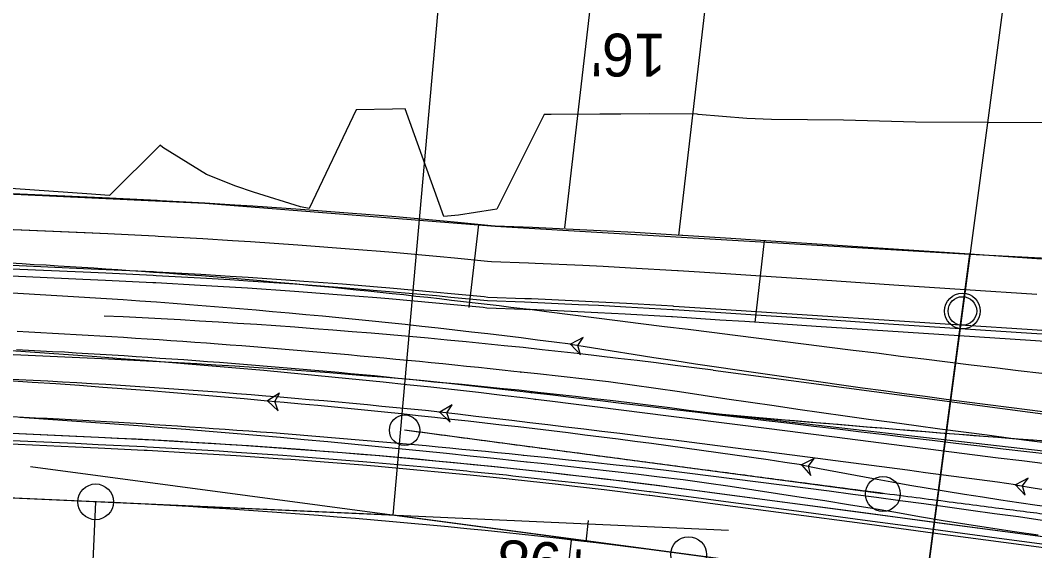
# Model space of a CAD drawing. Extents: x -70 to 701944, y -4 to 666871.
# Drawn here: x 667714.7 to 667856.7, y 656552.8 to 656627 of the extents above; entities that cross this region are included whole.
import ezdxf

# ---------------------------------------------------------------- set-up
doc = ezdxf.new("R2010")
doc.units = 0
for name, color, linetype in [('R_Detour', 7, 'Continuous'), ('R_Draft', 7, 'Continuous'), ('R_Drive', 7, 'Continuous'), ('R_Horz Alg', 7, 'Continuous'), ('R_Horz Alg Annot', 7, 'Continuous'), ('R_No Plot', 7, 'Continuous'), ('R_Proposed Const Limits', 7, 'Continuous'), ('R_Proposed Road', 7, 'Continuous'), ('R_ROW', 7, 'Continuous'), ('R_Striping', 7, 'Continuous'), ('R_Water', 7, 'Continuous'), ('T_Indications', 7, 'Continuous'), ('T_Vehicle Path Lt Minor', 7, 'Continuous'), ('T_Vehicle Path Rt', 7, 'Continuous')]:
    doc.layers.add(name, color=color, linetype=linetype)

msp = doc.modelspace()

# ---------------------------------------------------------------- linework, layer by layer
at = {"layer": 'R_Detour'}
msp.add_line((667852.89, 656633.86), (667841.43, 656547.81), dxfattribs=at)
at = {"layer": 'R_Draft'}
msp.add_line((667835.43, 656560.72), (667768.5, 656569.64), dxfattribs=at)
for centre, radius in [((667768.5, 656569.64), 2.13), ((667835.43, 656560.72), 2.44)]:
    msp.add_circle(centre, radius, dxfattribs=at)
msp.add_open_spline([(668503.19, 656560.73), (668456.49, 656569.75), (668425.89, 656581.27), (668346.17, 656570.41), (668185.6, 656628.5), (667984.84, 656548.03), (667888.17, 656554.09), (667835.43, 656560.72), (667768.5, 656569.64)], degree=2, dxfattribs=at)
at = {"layer": 'R_Drive'}
for p, q in [((667796.37, 656645.62), (667790.86, 656597.92)), ((667811.01, 656632.92), (667806.84, 656596.86)), ((667778.83, 656598.4), (667777.5, 656586.82)), ((667818.84, 656596.14), (667817.52, 656584.72))]:
    msp.add_line(p, q, dxfattribs=at)
at = {"layer": 'R_Horz Alg'}
for p, q in [((667725.26, 656559.62), (664961.47, 656684.5)), ((667766.92, 656557.74), (667725.26, 656559.62)), ((667808.24, 656552.24), (667766.92, 656557.74))]:
    msp.add_line(p, q, dxfattribs=at)
msp.add_lwpolyline([(667791.28, 656549.31), (667791.85, 656554.27)], dxfattribs=at)
for centre in [(667725.26, 656559.62), (667808.24, 656552.24)]:
    msp.add_circle(centre, 2.5, dxfattribs=at)
msp.add_arc((667682.16, 655605.67), 954.93, 82.41302, 87.41302, dxfattribs=at)
at = {"layer": 'R_Horz Alg Annot'}
for points in [[(667766.92, 656557.74), (667781.69, 656723.66)], [(667725.26, 656559.62), (667717.07, 656378.27)]]:
    msp.add_lwpolyline(points, dxfattribs=at)
at = {"layer": 'R_No Plot'}
for p, q in [((667813.84, 656555.62), (664810.54, 656691.32)), ((667725.26, 656559.62), (664961.47, 656684.5)), ((668021.72, 656523.8), (667716.14, 656564.5))]:
    msp.add_line(p, q, dxfattribs=at)
for points in [[(667694.03, 656603.58), (667740.56, 656601.38), (667781.16, 656598.17), (667847.62, 656594.24), (667841.43, 656547.81), (667766.92, 656557.74), (667692.11, 656561.12)], [(667847.62, 656594.24), (667899.28, 656591.58), (667960.86, 656591.75), (667973.35, 656591.19), (667970.89, 656536.74), (667900.78, 656539.91), (667841.43, 656547.81)], [(667692.11, 656561.12), (667689.65, 656506.68), (667773.86, 656501.24), (667833.59, 656488.96), (667841.45, 656547.81), (667766.92, 656557.74)]]:
    msp.add_lwpolyline(points, close=True, dxfattribs=at)
msp.add_circle((667846.56, 656586.31), 2.5, dxfattribs=at)
msp.add_arc((667682.16, 655605.67), 954.93, 82.41302, 87.41302, dxfattribs=at)
at = {"layer": 'R_Proposed Const Limits'}
for points in [[(667860.16, 656612.65), (667850.07, 656612.69), (667839.99, 656612.71), (667829.94, 656612.99), (667819.86, 656613.07), (667816.37, 656613.25), (667809.56, 656613.81), (667809.45, 656613.82), (667802.7, 656613.88), (667798.74, 656613.85), (667795.84, 656613.82), (667788.99, 656613.81), (667788.05, 656613.79), (667781.4, 656600.57), (667780.82, 656600.46), (667776.06, 656599.72), (667774, 656599.52), (667768.56, 656614.6), (667766.81, 656614.54), (667761.73, 656614.44), (667755.16, 656600.65), (667753.95, 656600.9), (667747.37, 656602.93), (667744.89, 656603.79), (667740.79, 656605.39), (667734.68, 656609.2), (667734.27, 656609.49), (667727.2, 656602.47)], [(667727.2, 656602.47), (667724.02, 656602.69), (667714.04, 656603.41), (667704.06, 656603.99), (667694.07, 656604.33), (667684.08, 656604.85), (667674.08, 656605.17)]]:
    msp.add_lwpolyline(points, dxfattribs=at)
at = {"layer": 'R_Proposed Road'}
for p, q in [((667725.67, 656568.61), (667418.1, 656582.51)), ((667860.64, 656554.34), (667809.43, 656561.16))]:
    msp.add_line(p, q, dxfattribs=at)
for points in [[(667857.62, 656593.58), (667847.62, 656594.24), (667837.62, 656594.9), (667827.61, 656595.56), (667817.61, 656596.22), (667814.13, 656596.45), (667807.42, 656596.89), (667807.31, 656596.89), (667800.72, 656597.28), (667796.85, 656597.49), (667794.01, 656597.63), (667787.3, 656597.93), (667786.39, 656597.97), (667781.16, 656598.17), (667780.6, 656598.23), (667775.96, 656598.68), (667773.94, 656598.86), (667767.27, 656599.46), (667765.55, 656599.6), (667760.59, 656600.01), (667755.14, 656600.42), (667753.92, 656600.51), (667747.24, 656600.97), (667744.72, 656601.13), (667740.56, 656601.38), (667734.29, 656601.73), (667733.87, 656601.75), (667727.18, 656602.08), (667724, 656602.22), (667714.01, 656602.67)], [(667856.96, 656588.62), (667846.96, 656589.28), (667836.95, 656589.94), (667826.95, 656590.6), (667816.95, 656591.26), (667813.47, 656591.49), (667806.8, 656591.93), (667806.69, 656591.93), (667800.12, 656592.32), (667796.27, 656592.52), (667793.45, 656592.66), (667786.78, 656592.96), (667785.86, 656593), (667780.66, 656593.2), (667780.11, 656593.25), (667775.49, 656593.7), (667773.48, 656593.89), (667766.84, 656594.48), (667765.14, 656594.62), (667760.2, 656595.02), (667754.78, 656595.44), (667753.56, 656595.52), (667746.91, 656595.98), (667744.41, 656596.14), (667740.26, 656596.39), (667734.03, 656596.74), (667733.61, 656596.76), (667726.96, 656597.08), (667723.78, 656597.23), (667713.79, 656597.68)], [(667864.41, 656582.63), (667856.23, 656583.17), (667846.23, 656583.83), (667836.23, 656584.49), (667826.23, 656585.15), (667816.23, 656585.81), (667812.75, 656586.04), (667806.11, 656586.47), (667806, 656586.48), (667799.47, 656586.85), (667795.64, 656587.06), (667792.83, 656587.19), (667786.2, 656587.49), (667785.29, 656587.53), (667780.11, 656587.72), (667779.57, 656587.78), (667774.97, 656588.22), (667772.97, 656588.41), (667766.37, 656589), (667764.68, 656589.14), (667759.77, 656589.54), (667754.37, 656589.95), (667753.16, 656590.04), (667746.55, 656590.49), (667744.06, 656590.65), (667739.94, 656590.9), (667733.74, 656591.25), (667733.33, 656591.27), (667726.71, 656591.59), (667723.53, 656591.73), (667713.54, 656592.18)], [(667864.47, 656583.13), (667856.3, 656583.67), (667846.3, 656584.33), (667836.29, 656584.98), (667826.29, 656585.64), (667816.29, 656586.3), (667812.81, 656586.53), (667806.17, 656586.96), (667806.06, 656586.97), (667799.53, 656587.35), (667795.7, 656587.55), (667792.89, 656587.69), (667786.25, 656587.99), (667785.34, 656588.02), (667780.16, 656588.22), (667779.62, 656588.27), (667775.02, 656588.72), (667773.02, 656588.91), (667766.41, 656589.49), (667764.72, 656589.64), (667759.81, 656590.04), (667754.41, 656590.45), (667753.2, 656590.54), (667746.59, 656590.99), (667744.09, 656591.15), (667739.97, 656591.4), (667733.77, 656591.75), (667733.35, 656591.77), (667726.73, 656592.09), (667723.55, 656592.23), (667713.56, 656592.68)], [(667864.28, 656581.64), (667856.1, 656582.18), (667846.1, 656582.84), (667836.1, 656583.5), (667826.1, 656584.16), (667816.1, 656584.82), (667812.61, 656585.05), (667805.98, 656585.48), (667805.87, 656585.48), (667799.35, 656585.86), (667795.53, 656586.06), (667792.72, 656586.2), (667786.09, 656586.5), (667785.19, 656586.53), (667780.01, 656586.73), (667779.47, 656586.78), (667774.88, 656587.23), (667772.88, 656587.41), (667766.29, 656588), (667764.59, 656588.14), (667759.69, 656588.54), (667754.3, 656588.95), (667753.09, 656589.04), (667746.49, 656589.49), (667744, 656589.65), (667739.88, 656589.9), (667733.69, 656590.25), (667733.27, 656590.27), (667726.66, 656590.59), (667723.48, 656590.73), (667713.49, 656591.19)], [(667860.64, 656554.34), (667852.53, 656555.42), (667842.62, 656556.74), (667832.71, 656558.06), (667822.8, 656559.38), (667812.88, 656560.7), (667809.43, 656561.16), (667803.01, 656561.99), (667802.91, 656562), (667796.59, 656562.78), (667792.89, 656563.21), (667790.16, 656563.53), (667783.73, 656564.23), (667782.85, 656564.32), (667777.83, 656564.84), (667777.3, 656564.89), (667772.81, 656565.32), (667770.85, 656565.51), (667764.41, 656566.08), (667762.75, 656566.22), (667757.96, 656566.61), (667752.69, 656567.01), (667751.51, 656567.1), (667745.05, 656567.54), (667742.62, 656567.7), (667738.59, 656567.94), (667732.54, 656568.28), (667732.13, 656568.3), (667725.67, 656568.61), (667722.49, 656568.76), (667712.5, 656569.21)], [(667860.44, 656552.85), (667852.33, 656553.93), (667842.42, 656555.25), (667832.51, 656556.57), (667822.6, 656557.89), (667812.68, 656559.21), (667809.23, 656559.67), (667802.83, 656560.5), (667802.72, 656560.51), (667796.41, 656561.29), (667792.71, 656561.72), (667790, 656562.03), (667783.57, 656562.74), (667782.7, 656562.83), (667777.68, 656563.34), (667777.15, 656563.4), (667772.67, 656563.83), (667770.72, 656564.01), (667764.28, 656564.59), (667762.63, 656564.73), (667757.84, 656565.11), (667752.58, 656565.52), (667751.4, 656565.6), (667744.95, 656566.04), (667742.53, 656566.2), (667738.51, 656566.44), (667732.46, 656566.78), (667732.06, 656566.8), (667725.6, 656567.11), (667722.42, 656567.26), (667712.43, 656567.71)], [(667860.44, 656552.85), (667852.33, 656553.93), (667842.42, 656555.25), (667832.51, 656556.57), (667822.6, 656557.89), (667812.68, 656559.21), (667809.23, 656559.67), (667802.83, 656560.5), (667802.72, 656560.51), (667796.41, 656561.29), (667792.71, 656561.72), (667790, 656562.03), (667783.57, 656562.74), (667782.7, 656562.83), (667777.68, 656563.34), (667777.15, 656563.4), (667772.67, 656563.83), (667770.72, 656564.01), (667764.28, 656564.59), (667762.63, 656564.73), (667757.84, 656565.11), (667752.58, 656565.52), (667751.4, 656565.6), (667744.95, 656566.04), (667742.53, 656566.2), (667738.51, 656566.44), (667732.46, 656566.78), (667732.06, 656566.8), (667725.6, 656567.11), (667722.42, 656567.26), (667712.43, 656567.71)], [(667860.51, 656553.34), (667852.4, 656554.42), (667842.49, 656555.74), (667832.58, 656557.06), (667822.66, 656558.39), (667812.75, 656559.71), (667809.3, 656560.17), (667802.89, 656561), (667802.78, 656561.01), (667796.47, 656561.79), (667792.77, 656562.22), (667790.05, 656562.53), (667783.63, 656563.23), (667782.75, 656563.33), (667777.73, 656563.84), (667777.2, 656563.89), (667772.71, 656564.33), (667770.76, 656564.51), (667764.32, 656565.08), (667762.67, 656565.22), (667757.88, 656565.61), (667752.62, 656566.01), (667751.44, 656566.1), (667744.99, 656566.54), (667742.56, 656566.7), (667738.54, 656566.94), (667732.49, 656567.28), (667732.08, 656567.3), (667725.63, 656567.61), (667722.44, 656567.76), (667712.45, 656568.21)], [(667860.51, 656553.34), (667852.4, 656554.42), (667842.49, 656555.74), (667832.58, 656557.06), (667822.66, 656558.39), (667812.75, 656559.71), (667809.3, 656560.17), (667802.89, 656561), (667802.78, 656561.01), (667796.47, 656561.79), (667792.77, 656562.22), (667790.05, 656562.53), (667783.63, 656563.23), (667782.75, 656563.33), (667777.73, 656563.84), (667777.2, 656563.89), (667772.71, 656564.33), (667770.76, 656564.51), (667764.32, 656565.08), (667762.67, 656565.22), (667757.88, 656565.61), (667752.62, 656566.01), (667751.44, 656566.1), (667744.99, 656566.54), (667742.56, 656566.7), (667738.54, 656566.94), (667732.49, 656567.28), (667732.08, 656567.3), (667725.63, 656567.61), (667722.44, 656567.76), (667712.45, 656568.21)], [(667860.64, 656554.34), (667852.53, 656555.42), (667842.62, 656556.74), (667832.71, 656558.06), (667822.8, 656559.38), (667812.88, 656560.7), (667809.43, 656561.16), (667803.01, 656561.99), (667802.91, 656562), (667796.59, 656562.78), (667792.89, 656563.21), (667790.16, 656563.53), (667783.73, 656564.23), (667782.85, 656564.32), (667777.83, 656564.84), (667777.3, 656564.89), (667772.81, 656565.32), (667770.85, 656565.51), (667764.41, 656566.08), (667762.75, 656566.22), (667757.96, 656566.61), (667752.69, 656567.01), (667751.51, 656567.1), (667745.05, 656567.54), (667742.62, 656567.7), (667738.59, 656567.94), (667736.36, 656568.07)]]:
    msp.add_lwpolyline(points, dxfattribs=at)
msp.add_arc((667682.16, 655605.67), 963.93, 82.41302, 87.41302, dxfattribs=at)
at = {"layer": 'R_ROW'}
msp.add_line((667794.19, 656557.02), (667793.84, 656554.04), dxfattribs=at)
at = {"layer": 'R_Striping'}
msp.add_line((667862.22, 656566.23), (667810.88, 656572.06), dxfattribs=at)
msp.add_lwpolyline([(667726.16, 656579.6), (667726.15, 656579.6), (667418.43, 656593.51), (667318.67, 656601.02), (667119.04, 656610.04)], dxfattribs=at)
for centre, radius, start, end in [((667682.16, 655605.67), 974.93, 82.41302, 87.41302), ((668081.19, 659555.15), 2995.31, 264.82247, 267.36643), ((668081.19, 659555.15), 2995.31, 264.82247, 267.31937)]:
    msp.add_arc(centre, radius, start, end, dxfattribs=at)
at = {"layer": 'R_Water'}
msp.add_circle((667846.56, 656586.31), 2, dxfattribs=at)
at = {"layer": 'T_Indications'}
for p, q in [((667727.18, 656602.08), (667419.75, 656615.97)), ((667726.96, 656597.08), (667419.38, 656610.98))]:
    msp.add_line(p, q, dxfattribs=at)
at = {"layer": 'T_Vehicle Path Lt Minor'}
for points in [[(667786.81, 656573.95), (667785.48, 656574.12), (667782.15, 656574.51), (667778.82, 656574.89), (667775.48, 656575.27), (667772.15, 656575.64), (667768.81, 656576), (667765.48, 656576.34), (667762.14, 656576.69), (667758.8, 656577.02), (667755.46, 656577.34), (667752.12, 656577.66), (667748.78, 656577.97), (667745.44, 656578.27), (667742.11, 656578.56), (667738.78, 656578.84), (667735.44, 656579.12), (667732.11, 656579.39), (667728.77, 656579.64), (667725.44, 656579.9), (667722.1, 656580.14), (667718.77, 656580.38), (667715.43, 656580.6), (667712.09, 656580.82)], [(667858.14, 656564.93), (667854.86, 656565.34), (667851.58, 656565.75), (667848.3, 656566.17), (667845.03, 656566.58), (667841.75, 656567), (667838.47, 656567.42), (667835.2, 656567.83), (667831.92, 656568.25), (667828.64, 656568.67), (667825.35, 656569.08), (667822.07, 656569.5), (667818.76, 656569.92), (667815.44, 656570.34), (667812.11, 656570.76), (667808.78, 656571.19), (667805.45, 656571.61), (667802.13, 656572.03), (667798.8, 656572.45), (667795.47, 656572.88), (667792.14, 656573.3), (667788.81, 656573.71), (667786.81, 656573.95)], [(667785.61, 656565.19), (667784.29, 656565.33), (667780.97, 656565.69), (667777.66, 656566.03), (667774.34, 656566.38), (667771.03, 656566.71), (667767.71, 656567.05), (667764.4, 656567.37), (667761.08, 656567.69), (667757.76, 656568), (667754.44, 656568.3), (667751.12, 656568.6), (667747.81, 656568.89), (667744.49, 656569.17), (667741.17, 656569.45), (667737.86, 656569.72), (667734.55, 656569.98), (667731.23, 656570.23), (667727.92, 656570.48), (667724.6, 656570.72), (667721.29, 656570.96), (667717.97, 656571.18), (667714.66, 656571.4)], [(667857.15, 656554.97), (667853.83, 656555.44), (667850.5, 656555.94), (667847.18, 656556.45), (667843.87, 656556.98), (667840.55, 656557.54), (667837.24, 656558.11), (667833.93, 656558.67), (667830.62, 656559.21), (667827.31, 656559.74), (667823.99, 656560.25), (667820.68, 656560.76), (667817.37, 656561.26), (667814.07, 656561.75), (667810.77, 656562.22), (667807.47, 656562.69), (667804.16, 656563.08), (667800.85, 656563.47), (667797.54, 656563.85), (667794.23, 656564.23), (667790.91, 656564.6), (667787.6, 656564.97), (667785.61, 656565.19)]]:
    msp.add_lwpolyline(points, dxfattribs=at)
for points in [[(667749.32, 656573.73), (667750.79, 656572.37), (667750.32, 656573.64), (667751.01, 656574.8)], [(667824.02, 656564.8), (667825.34, 656563.3), (667825, 656564.61), (667825.82, 656565.69)]]:
    msp.add_lwpolyline(points, close=True, dxfattribs=at)
for centre in [(667749.32, 656573.73), (667749.32, 656573.73), (667786.81, 656573.95), (667786.81, 656573.95), (667785.61, 656565.19), (667785.61, 656565.19), (667824.02, 656564.8), (667824.02, 656564.8)]:
    msp.add_circle(centre, 0.0417, dxfattribs=at)
for centre, radius, start, end in [((667621.29, 655168.15), 1411.39, 84.79522, 89.08689), ((667636.92, 655315.4), 1263.33, 81.48297, 84.89542), ((667939.21, 657140.12), 586.74, 258.67796, 266.72473)]:
    msp.add_arc(centre, radius, start, end, dxfattribs=at)
at = {"layer": 'T_Vehicle Path Rt'}
msp.add_line((667862.88, 656571.19), (667811.68, 656578.01), dxfattribs=at)
for points in [[(667786.04, 656586.5), (667785.04, 656586.62), (667783.38, 656586.82), (667781.72, 656587.02), (667780.05, 656587.22), (667778.39, 656587.41), (667776.73, 656587.61), (667775.06, 656587.8), (667773.4, 656587.99), (667771.73, 656588.18), (667770.07, 656588.36), (667768.4, 656588.55), (667766.74, 656588.72), (667765.07, 656588.9), (667763.41, 656589.07), (667761.74, 656589.24), (667760.08, 656589.41), (667758.41, 656589.58), (667756.74, 656589.74), (667755.07, 656589.9), (667753.41, 656590.05), (667751.74, 656590.21), (667750.07, 656590.36), (667748.4, 656590.51), (667746.73, 656590.65), (667745.06, 656590.79), (667743.4, 656590.93), (667741.73, 656591.07), (667740.06, 656591.21), (667738.39, 656591.34), (667736.72, 656591.47), (667735.05, 656591.59), (667733.38, 656591.71), (667731.7, 656591.83), (667730.03, 656591.95), (667728.36, 656592.07), (667726.69, 656592.18), (667725.02, 656592.29), (667723.35, 656592.39), (667721.68, 656592.5), (667720, 656592.6), (667718.33, 656592.7), (667716.66, 656592.79), (667714.99, 656592.89), (667713.32, 656592.98)], [(667857.68, 656577.55), (667854.38, 656577.94), (667851.08, 656578.34), (667847.78, 656578.74), (667844.48, 656579.15), (667841.18, 656579.56), (667837.88, 656579.97), (667834.58, 656580.39), (667831.28, 656580.8), (667827.98, 656581.22), (667824.68, 656581.63), (667821.38, 656582.04), (667818.07, 656582.46), (667814.77, 656582.87), (667811.47, 656583.29), (667808.17, 656583.7), (667804.87, 656584.11), (667801.57, 656584.53), (667798.27, 656584.94), (667794.97, 656585.36), (667791.67, 656585.77), (667788.37, 656586.2), (667786.04, 656586.5)], [(667784.77, 656577.77), (667783.78, 656577.87), (667782.13, 656578.05), (667780.48, 656578.22), (667778.82, 656578.39), (667777.17, 656578.57), (667775.52, 656578.73), (667773.86, 656578.9), (667772.21, 656579.06), (667770.56, 656579.23), (667768.9, 656579.39), (667767.25, 656579.55), (667765.6, 656579.7), (667763.94, 656579.86), (667762.29, 656580.01), (667760.63, 656580.16), (667758.98, 656580.31), (667757.33, 656580.46), (667755.67, 656580.6), (667754.02, 656580.74), (667752.36, 656580.88), (667750.71, 656581.02), (667749.05, 656581.15), (667747.39, 656581.29), (667745.74, 656581.42), (667744.08, 656581.54), (667742.43, 656581.67), (667740.77, 656581.79), (667739.12, 656581.91), (667737.46, 656582.03), (667735.8, 656582.15), (667734.15, 656582.26), (667732.49, 656582.38), (667730.83, 656582.48), (667729.18, 656582.59), (667727.52, 656582.7), (667725.86, 656582.8), (667724.2, 656582.9), (667722.55, 656583), (667720.89, 656583.09), (667719.23, 656583.18), (667717.57, 656583.27), (667715.92, 656583.36), (667714.26, 656583.44)], [(667786.24, 656574.88), (667785.9, 656574.92), (667784.24, 656575.11), (667782.58, 656575.3), (667780.92, 656575.49), (667779.26, 656575.67), (667777.6, 656575.85), (667775.93, 656576.03), (667774.27, 656576.21), (667772.61, 656576.38), (667770.94, 656576.56), (667769.28, 656576.73), (667767.61, 656576.89), (667765.95, 656577.06), (667764.28, 656577.22), (667762.61, 656577.38), (667760.95, 656577.53), (667759.28, 656577.69), (667757.61, 656577.84), (667755.95, 656577.99), (667754.28, 656578.13), (667752.61, 656578.28), (667750.94, 656578.42), (667749.27, 656578.56), (667747.61, 656578.69), (667745.94, 656578.83), (667744.27, 656578.96), (667742.6, 656579.09), (667740.93, 656579.21), (667739.26, 656579.34), (667737.59, 656579.46), (667735.92, 656579.57), (667734.25, 656579.69), (667732.58, 656579.8), (667730.91, 656579.91), (667729.24, 656580.02), (667727.57, 656580.13), (667725.9, 656580.23), (667724.22, 656580.33), (667722.55, 656580.43), (667720.88, 656580.53), (667719.21, 656580.62), (667717.54, 656580.71), (667715.87, 656580.8), (667714.19, 656580.88)], [(667859.96, 656567.66), (667856.64, 656568.08), (667853.33, 656568.5), (667850.01, 656568.93), (667846.7, 656569.36), (667843.38, 656569.8), (667840.07, 656570.25), (667836.75, 656570.7), (667833.44, 656571.15), (667830.13, 656571.62), (667826.82, 656572.08), (667823.51, 656572.55), (667820.2, 656573.03), (667816.89, 656573.51), (667813.59, 656574), (667810.28, 656574.49), (667806.97, 656574.99), (667803.67, 656575.49), (667800.36, 656575.96), (667797.05, 656576.4), (667793.73, 656576.78), (667790.41, 656577.15), (667787.08, 656577.52), (667784.77, 656577.77)], [(667858.87, 656566.24), (667855.58, 656566.62), (667852.28, 656567.01), (667848.98, 656567.4), (667845.66, 656567.8), (667842.34, 656568.19), (667839.02, 656568.59), (667835.7, 656568.98), (667832.38, 656569.38), (667829.07, 656569.77), (667825.75, 656570.17), (667822.43, 656570.57), (667819.11, 656570.96), (667815.79, 656571.36), (667812.47, 656571.75), (667809.15, 656572.15), (667805.83, 656572.55), (667802.5, 656572.94), (667799.18, 656573.34), (667795.86, 656573.73), (667792.54, 656574.13), (667789.22, 656574.53), (667786.24, 656574.88)], [(667785.15, 656566.12), (667784.81, 656566.15), (667783.15, 656566.32), (667781.49, 656566.48), (667779.83, 656566.64), (667778.17, 656566.8), (667776.51, 656566.96), (667774.85, 656567.12), (667773.19, 656567.28), (667771.53, 656567.43), (667769.87, 656567.58), (667768.21, 656567.73), (667766.55, 656567.88), (667764.9, 656568.03), (667763.24, 656568.17), (667761.59, 656568.31), (667759.93, 656568.45), (667758.27, 656568.59), (667756.62, 656568.73), (667754.96, 656568.86), (667753.31, 656568.99), (667751.65, 656569.12), (667749.99, 656569.25), (667748.34, 656569.37), (667746.68, 656569.5), (667745.02, 656569.62), (667743.37, 656569.74), (667741.71, 656569.85), (667740.05, 656569.97), (667738.4, 656570.08), (667736.74, 656570.19), (667735.08, 656570.3), (667733.42, 656570.41), (667731.77, 656570.51), (667730.11, 656570.61), (667728.45, 656570.71), (667726.79, 656570.81), (667725.13, 656570.9), (667723.48, 656571), (667721.82, 656571.09), (667720.16, 656571.17), (667718.5, 656571.26), (667716.84, 656571.34), (667715.18, 656571.43), (667713.53, 656571.5)], [(667857.72, 656557.03), (667854.4, 656557.5), (667851.07, 656557.96), (667847.76, 656558.42), (667844.45, 656558.87), (667841.14, 656559.32), (667837.83, 656559.77), (667834.52, 656560.21), (667831.21, 656560.65), (667827.91, 656561.09), (667824.6, 656561.52), (667821.29, 656561.95), (667817.97, 656562.38), (667814.66, 656562.8), (667811.35, 656563.22), (667808.04, 656563.64), (667804.73, 656564.03), (667801.41, 656564.4), (667798.09, 656564.76), (667794.77, 656565.12), (667791.45, 656565.47), (667788.13, 656565.81), (667785.15, 656566.12)]]:
    msp.add_lwpolyline(points, dxfattribs=at)
for points in [[(667791.73, 656581.66), (667793.11, 656580.2), (667792.72, 656581.5), (667793.49, 656582.61)], [(667773.43, 656572.16), (667774.87, 656570.77), (667774.42, 656572.05), (667775.15, 656573.19)], [(667853.97, 656562.01), (667855.33, 656560.54), (667854.96, 656561.84), (667855.74, 656562.94)]]:
    msp.add_lwpolyline(points, close=True, dxfattribs=at)
for centre in [(667786.04, 656586.5), (667786.04, 656586.5), (667791.73, 656581.66), (667791.73, 656581.66), (667784.77, 656577.77), (667784.77, 656577.77), (667786.24, 656574.88), (667786.24, 656574.88), (667773.43, 656572.16), (667773.43, 656572.16), (667785.15, 656566.12), (667785.15, 656566.12), (667853.97, 656562.01), (667853.97, 656562.01)]:
    msp.add_circle(centre, 0.0417, dxfattribs=at)
for centre, radius, start, end in [((667659.51, 655565.03), 1025.19, 82.58996, 90.92563), ((667682.16, 655605.67), 980.93, 82.41302, 87.41302), ((668101.59, 658521.95), 1964.88, 260.92663, 263.67927), ((667658.12, 655456.84), 1121.27, 84.09746, 90.76297), ((667288.21, 652398.25), 4202.02, 82.2622, 83.36911), ((667964.15, 657204.36), 651.73, 260.26721, 268.10595)]:
    msp.add_arc(centre, radius, start, end, dxfattribs=at)

# ---------------------------------------------------------------- texts
at = {"layer": 'R_Drive'}
for s, rotation, p in [("16'", 179.7886, (667805.07, 656625.08)), ('+98', 177.0622, (667795.24, 656553.63))]:
    msp.add_text(s, height=6, rotation=rotation, dxfattribs=at).set_placement(p)
at = {"layer": 'R_No Plot'}
msp.add_text('+', height=0.1, rotation=173.2841, dxfattribs=at).set_placement((667793.89, 656554.09))

doc.saveas('drawing.dxf')
